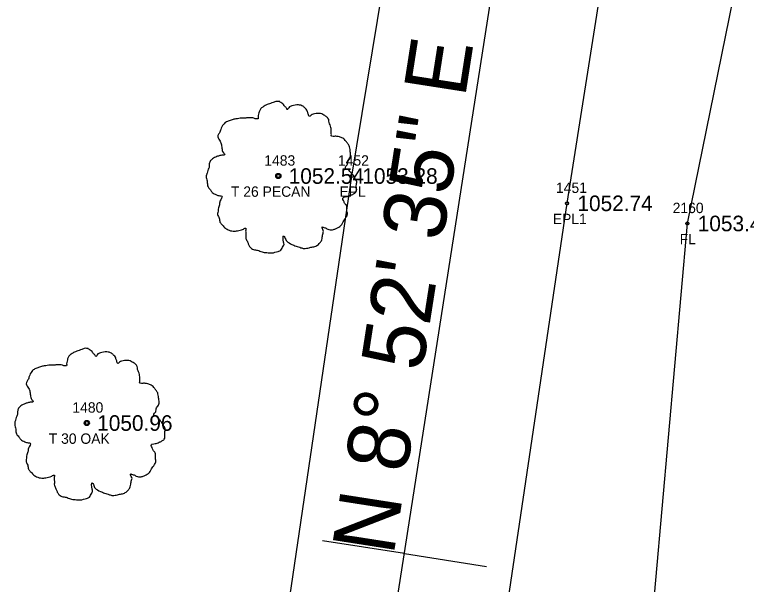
# Model space of a CAD drawing. Extents: x 1578957 to 1581675, y 1115963 to 1120391.
# Drawn here: x 1579746.4 to 1579816.9, y 1117901.5 to 1117956.4 of the extents above; entities that cross this region are included whole.
import ezdxf

# ---------------------------------------------------------------- set-up
doc = ezdxf.new("R2010")
doc.units = 0
for name, color, linetype in [('RD_EX_Fence_Other', 7, 'Continuous'), ('RD_EX_Fence_Other_txCode', 7, 'Continuous'), ('RD_EX_Road', 7, 'Continuous'), ('RD_EX_Road_txCode', 7, 'Continuous'), ('RD_EX_TX_Fence_Other_ELEV', 7, 'Continuous'), ('RD_EX_TX_Road_ELEV', 7, 'Continuous'), ('RD_EX_TX_VEG_ELEV', 7, 'Continuous'), ('RD_EX_VEG', 7, 'Continuous'), ('RD_EX_VEG_txCode', 7, 'Continuous'), ('RD_HC_Cl', 7, 'Continuous'), ('RD_HC_Data', 7, 'Continuous'), ('RD_HC_Data_Tic', 7, 'Continuous'), ('RD_SMD_Locator', 7, 'Continuous')]:
    doc.layers.add(name, color=color, linetype=linetype)

msp = doc.modelspace()

# ---------------------------------------------------------------- linework, layer by layer
at = {"layer": 'RD_EX_Fence_Other'}
msp.add_lwpolyline([(1579823.104, 1118041.087), (1579819.64, 1117977.762), (1579811.21, 1117936.274), (1579806.912, 1117888.201), (1579805.65, 1117872.977), (1579810.216, 1117834.804), (1579821.355, 1117805.105), (1579835.234, 1117784.194), (1579851.403, 1117768.05), (1579868.554, 1117757.557), (1579908.33, 1117744.227), (1579949.735, 1117742.637), (1579998.853, 1117745.107), (1580033.637, 1117749.157), (1580057.075, 1117744.228), (1580092.078, 1117730.794), (1580117.524, 1117724.619), (1580141.715, 1117727.925), (1580159.983, 1117735.31), (1580192.445, 1117760.446), (1580226.972, 1117787.769), (1580271.309, 1117822.486), (1580302.096, 1117858.032)], dxfattribs=at)
at = {"layer": 'RD_EX_Road'}
for points in [[(1580132.914, 1117689.949), (1580126.197, 1117690.713), (1580104.514, 1117701.773), (1580054.231, 1117722.915), (1579999.655, 1117728.645), (1579947.034, 1117725.641), (1579902.617, 1117727.901), (1579859.282, 1117741.23), (1579828.335, 1117764.868), (1579804.422, 1117802.726), (1579793.197, 1117845.912), (1579792.758, 1117891.982), (1579799.628, 1117938.215), (1579807.414, 1117987.508), (1579809.684, 1118039.768), (1579804.464, 1118093.359), (1579794.793, 1118143.944)], [(1580121.995, 1117647.598), (1580119.902, 1117658.172), (1580108.554, 1117670.894), (1580093.888, 1117680.496), (1580047.657, 1117700.115), (1579998.943, 1117706.513), (1579949.017, 1117704.446), (1579899.181, 1117706.754), (1579851.312, 1117721.596), (1579810.789, 1117752.923), (1579804.028, 1117759.706), (1579792.304, 1117778.187), (1579787.439, 1117787.947), (1579779.119, 1117811.184), (1579772.603, 1117842.297), (1579771.808, 1117848.588), (1579770.145, 1117878.236), (1579771.725, 1117892.019), (1579778.922, 1117940.842), (1579785.853, 1117982.888), (1579786.73, 1117990.339), (1579789.156, 1118040.245), (1579783.452, 1118089.738), (1579774.288, 1118139.394)]]:
    msp.add_lwpolyline(points, dxfattribs=at)
at = {"layer": 'RD_EX_VEG'}
for centre, radius in [((1579771.829, 1117940.842), 0.25), ((1579771.816, 1117940.823), 0.0001), ((1579753.39, 1117917.061), 0.25), ((1579753.377, 1117917.042), 0.0001)]:
    msp.add_circle(centre, radius, dxfattribs=at)
for points in [[(1579771.96, 1117948.009), (1579771.661, 1117948.034), (1579771.336, 1117947.934), (1579771.086, 1117947.835), (1579770.861, 1117947.76), (1579770.636, 1117947.66), (1579770.336, 1117947.485), (1579770.111, 1117947.285), (1579769.986, 1117947.035), (1579769.936, 1117946.81), (1579769.886, 1117946.535), (1579769.886, 1117946.36), (1579769.761, 1117946.335), (1579769.611, 1117946.36), (1579769.362, 1117946.435), (1579769.112, 1117946.435), (1579768.862, 1117946.435), (1579768.512, 1117946.41), (1579768.162, 1117946.41), (1579767.887, 1117946.36), (1579767.562, 1117946.31), (1579767.188, 1117946.185), (1579766.838, 1117946.06), (1579766.538, 1117945.81), (1579766.288, 1117945.336), (1579766.163, 1117944.986), (1579766.013, 1117944.736), (1579766.163, 1117944.286), (1579766.338, 1117943.936), (1579766.363, 1117943.736), (1579766.438, 1117943.312), (1579766.538, 1117943.087), (1579766.663, 1117942.887), (1579766.588, 1117942.862), (1579766.213, 1117942.812), (1579765.913, 1117942.712), (1579765.488, 1117942.487), (1579765.263, 1117942.262), (1579765.163, 1117941.937), (1579765.138, 1117941.587), (1579765.039, 1117941.387), (1579764.964, 1117941.112), (1579764.939, 1117941.037), (1579764.889, 1117940.713), (1579764.989, 1117940.263), (1579765.014, 1117939.913), (1579765.138, 1117939.688), (1579765.288, 1117939.513), (1579765.463, 1117939.263), (1579765.863, 1117939.038), (1579766.188, 1117938.938), (1579766.388, 1117938.913), (1579766.213, 1117938.414), (1579766.163, 1117938.064), (1579766.038, 1117937.664), (1579766.038, 1117937.589), (1579765.988, 1117937.114), (1579766.138, 1117936.789), (1579766.213, 1117936.415), (1579766.388, 1117936.19), (1579766.663, 1117935.89), (1579766.988, 1117935.665), (1579767.487, 1117935.54), (1579767.887, 1117935.565), (1579768.462, 1117935.74), (1579768.712, 1117935.815), (1579768.687, 1117935.64), (1579768.712, 1117935.265), (1579768.712, 1117934.84), (1579768.862, 1117934.515), (1579768.962, 1117934.24), (1579769.112, 1117933.991), (1579769.437, 1117933.766), (1579769.836, 1117933.691), (1579770.261, 1117933.541), (1579770.711, 1117933.466), (1579771.211, 1117933.441), (1579771.811, 1117933.591), (1579772.085, 1117933.716), (1579772.185, 1117933.891), (1579772.385, 1117934.265), (1579772.335, 1117934.49), (1579772.36, 1117935.09), (1579772.46, 1117934.915), (1579772.635, 1117934.565), (1579773.135, 1117934.265), (1579773.535, 1117934.091), (1579774.01, 1117933.941), (1579774.309, 1117933.866), (1579774.784, 1117933.941), (1579775.159, 1117934.016), (1579775.534, 1117934.141), (1579775.834, 1117934.415), (1579776.009, 1117934.69), (1579776.059, 1117934.965), (1579776.134, 1117935.34), (1579776.184, 1117935.515)], [(1579776.184, 1117935.515), (1579776.109, 1117935.69), (1579776.059, 1117935.94), (1579776.134, 1117935.915), (1579776.309, 1117935.865), (1579776.583, 1117935.74), (1579776.808, 1117935.665), (1579777.133, 1117935.69), (1579777.408, 1117935.79), (1579777.858, 1117936.065), (1579778.133, 1117936.539), (1579778.408, 1117936.939), (1579778.483, 1117937.264), (1579778.433, 1117937.489), (1579778.408, 1117937.989), (1579778.208, 1117938.239), (1579778.158, 1117938.364), (1579778.058, 1117938.763), (1579778.133, 1117938.813), (1579778.408, 1117938.863), (1579778.782, 1117938.988), (1579779.057, 1117939.113), (1579779.282, 1117939.288), (1579779.357, 1117939.513), (1579779.332, 1117939.913), (1579779.382, 1117940.313), (1579779.307, 1117940.463), (1579779.207, 1117940.613), (1579779.132, 1117940.813), (1579778.982, 1117940.962), (1579778.882, 1117941.112), (1579778.782, 1117941.212), (1579778.658, 1117941.362), (1579778.483, 1117941.487), (1579778.333, 1117941.537), (1579778.283, 1117941.687), (1579778.433, 1117941.887), (1579778.483, 1117941.987), (1579778.508, 1117942.212), (1579778.733, 1117942.562), (1579778.782, 1117942.962), (1579778.733, 1117943.386), (1579778.683, 1117943.661), (1579778.533, 1117943.936), (1579778.333, 1117944.186), (1579778.208, 1117944.361), (1579778.033, 1117944.486), (1579777.708, 1117944.611), (1579777.458, 1117944.661), (1579777.108, 1117944.661), (1579776.908, 1117944.711), (1579776.933, 1117944.761), (1579776.933, 1117944.911), (1579776.933, 1117945.186), (1579776.858, 1117945.635), (1579776.708, 1117946.135), (1579776.708, 1117946.16), (1579776.608, 1117946.41), (1579776.384, 1117946.61), (1579776.209, 1117946.71), (1579776.009, 1117946.835), (1579775.759, 1117946.86), (1579775.459, 1117946.86), (1579775.184, 1117946.81), (1579774.984, 1117946.71), (1579774.809, 1117946.585), (1579774.734, 1117946.735), (1579774.634, 1117947.035), (1579774.584, 1117947.185), (1579774.434, 1117947.36), (1579774.21, 1117947.56), (1579773.76, 1117947.685), (1579773.135, 1117947.61), (1579772.835, 1117947.41), (1579772.685, 1117947.235), (1579772.635, 1117947.36), (1579772.435, 1117947.56), (1579772.335, 1117947.735), (1579772.16, 1117947.86), (1579772.01, 1117947.959), (1579771.91, 1117948.009)], [(1579753.522, 1117924.228), (1579753.222, 1117924.253), (1579752.897, 1117924.153), (1579752.647, 1117924.053), (1579752.422, 1117923.978), (1579752.197, 1117923.878), (1579751.897, 1117923.703), (1579751.672, 1117923.503), (1579751.547, 1117923.253), (1579751.497, 1117923.028), (1579751.448, 1117922.753), (1579751.448, 1117922.578), (1579751.323, 1117922.553), (1579751.173, 1117922.578), (1579750.923, 1117922.653), (1579750.673, 1117922.653), (1579750.423, 1117922.653), (1579750.073, 1117922.628), (1579749.723, 1117922.628), (1579749.448, 1117922.578), (1579749.124, 1117922.529), (1579748.749, 1117922.404), (1579748.399, 1117922.279), (1579748.099, 1117922.029), (1579747.849, 1117921.554), (1579747.724, 1117921.204), (1579747.574, 1117920.954), (1579747.724, 1117920.504), (1579747.899, 1117920.154), (1579747.924, 1117919.955), (1579747.999, 1117919.53), (1579748.099, 1117919.305), (1579748.224, 1117919.105), (1579748.149, 1117919.08), (1579747.774, 1117919.03), (1579747.474, 1117918.93), (1579747.049, 1117918.705), (1579746.825, 1117918.48), (1579746.725, 1117918.155), (1579746.7, 1117917.806), (1579746.6, 1117917.606), (1579746.525, 1117917.331), (1579746.5, 1117917.256), (1579746.45, 1117916.931), (1579746.55, 1117916.481), (1579746.575, 1117916.131), (1579746.7, 1117915.906), (1579746.85, 1117915.731), (1579747.024, 1117915.482), (1579747.424, 1117915.257), (1579747.749, 1117915.157), (1579747.949, 1117915.132), (1579747.774, 1117914.632), (1579747.724, 1117914.282), (1579747.599, 1117913.882), (1579747.599, 1117913.807), (1579747.549, 1117913.333), (1579747.699, 1117913.008), (1579747.774, 1117912.633), (1579747.949, 1117912.408), (1579748.224, 1117912.108), (1579748.549, 1117911.883), (1579749.049, 1117911.758), (1579749.448, 1117911.783), (1579750.023, 1117911.958), (1579750.273, 1117912.033), (1579750.248, 1117911.858), (1579750.273, 1117911.483), (1579750.273, 1117911.059), (1579750.423, 1117910.734), (1579750.523, 1117910.459), (1579750.673, 1117910.209), (1579750.998, 1117909.984), (1579751.398, 1117909.909), (1579751.822, 1117909.759), (1579752.272, 1117909.684), (1579752.772, 1117909.659), (1579753.372, 1117909.809), (1579753.647, 1117909.934), (1579753.747, 1117910.109), (1579753.946, 1117910.484), (1579753.896, 1117910.709), (1579753.921, 1117911.308), (1579754.021, 1117911.133), (1579754.196, 1117910.784), (1579754.696, 1117910.484), (1579755.096, 1117910.309), (1579755.571, 1117910.159), (1579755.871, 1117910.084), (1579756.345, 1117910.159), (1579756.72, 1117910.234), (1579757.095, 1117910.359), (1579757.395, 1117910.634), (1579757.57, 1117910.909), (1579757.62, 1117911.183), (1579757.695, 1117911.558), (1579757.745, 1117911.733)], [(1579757.745, 1117911.733), (1579757.67, 1117911.908), (1579757.62, 1117912.158), (1579757.695, 1117912.133), (1579757.87, 1117912.083), (1579758.145, 1117911.958), (1579758.37, 1117911.883), (1579758.694, 1117911.908), (1579758.969, 1117912.008), (1579759.419, 1117912.283), (1579759.694, 1117912.758), (1579759.969, 1117913.158), (1579760.044, 1117913.482), (1579759.994, 1117913.707), (1579759.969, 1117914.207), (1579759.769, 1117914.457), (1579759.719, 1117914.582), (1579759.619, 1117914.982), (1579759.694, 1117915.032), (1579759.969, 1117915.082), (1579760.344, 1117915.207), (1579760.619, 1117915.332), (1579760.843, 1117915.507), (1579760.918, 1117915.731), (1579760.893, 1117916.131), (1579760.943, 1117916.531), (1579760.868, 1117916.681), (1579760.768, 1117916.831), (1579760.693, 1117917.031), (1579760.544, 1117917.181), (1579760.444, 1117917.331), (1579760.344, 1117917.431), (1579760.219, 1117917.581), (1579760.044, 1117917.706), (1579759.894, 1117917.756), (1579759.844, 1117917.905), (1579759.994, 1117918.105), (1579760.044, 1117918.205), (1579760.069, 1117918.43), (1579760.294, 1117918.78), (1579760.344, 1117919.18), (1579760.294, 1117919.605), (1579760.244, 1117919.88), (1579760.094, 1117920.154), (1579759.894, 1117920.404), (1579759.769, 1117920.579), (1579759.594, 1117920.704), (1579759.269, 1117920.829), (1579759.019, 1117920.879), (1579758.669, 1117920.879), (1579758.469, 1117920.929), (1579758.494, 1117920.979), (1579758.494, 1117921.129), (1579758.494, 1117921.404), (1579758.419, 1117921.854), (1579758.27, 1117922.354), (1579758.27, 1117922.379), (1579758.17, 1117922.628), (1579757.945, 1117922.828), (1579757.77, 1117922.928), (1579757.57, 1117923.053), (1579757.32, 1117923.078), (1579757.02, 1117923.078), (1579756.745, 1117923.028), (1579756.545, 1117922.928), (1579756.37, 1117922.803), (1579756.295, 1117922.953), (1579756.195, 1117923.253), (1579756.145, 1117923.403), (1579755.996, 1117923.578), (1579755.771, 1117923.778), (1579755.321, 1117923.903), (1579754.696, 1117923.828), (1579754.396, 1117923.628), (1579754.246, 1117923.453), (1579754.196, 1117923.578), (1579753.996, 1117923.778), (1579753.896, 1117923.953), (1579753.722, 1117924.078), (1579753.572, 1117924.178), (1579753.472, 1117924.228)]]:
    msp.add_spline(points, degree=3, dxfattribs=at)
at = {"layer": 'RD_HC_Cl'}
msp.add_line((1579781.145, 1117886.379), (1579795.16, 1117976.12), dxfattribs=at)
at = {"layer": 'RD_HC_Data_Tic'}
for q in [(1579776.07, 1117905.73), (1579791.879, 1117903.261)]:
    msp.add_line((1579783.974, 1117904.496), q, dxfattribs=at)
at = {"layer": 'RD_SMD_Locator'}
for centre in [(1579771.829, 1117940.842), (1579778.922, 1117940.842), (1579799.628, 1117938.215), (1579811.21, 1117936.274), (1579753.39, 1117917.06)]:
    msp.add_circle(centre, 0.15, dxfattribs=at)

# ---------------------------------------------------------------- texts
at = {"layer": 'RD_EX_Fence_Other_txCode'}
for s, p in [('2160', (1579809.8, 1117937.274)), ('FL', (1579810.478, 1117934.274))]:
    msp.add_text(s, height=1, dxfattribs=at).set_placement(p)
at = {"layer": 'RD_EX_Road_txCode'}
for s, p in [('1452', (1579777.576, 1117941.842)), ('1451', (1579798.565, 1117939.215)), ('EPL', (1579777.717, 1117938.842)), ('EPL1', (1579798.258, 1117936.215))]:
    msp.add_text(s, height=1, dxfattribs=at).set_placement(p)
at = {"layer": 'RD_EX_TX_Fence_Other_ELEV'}
msp.add_text('1053.47', height=1.5, dxfattribs=at).set_placement((1579812.21, 1117935.524))
at = {"layer": 'RD_EX_TX_Road_ELEV'}
for s, p in [('1053.28', (1579779.922, 1117940.092)), ('1052.74', (1579800.628, 1117937.465))]:
    msp.add_text(s, height=1.5, dxfattribs=at).set_placement(p)
at = {"layer": 'RD_EX_TX_VEG_ELEV'}
for s, p in [('1052.54', (1579772.829, 1117940.092)), ('1050.96', (1579754.39, 1117916.31))]:
    msp.add_text(s, height=1.5, dxfattribs=at).set_placement(p)
at = {"layer": 'RD_EX_VEG_txCode'}
for s, p in [('1483', (1579770.482, 1117941.842)), ('T 26 PECAN', (1579767.269, 1117938.842)), ('1480', (1579752.004, 1117918.06)), ('T 30 OAK', (1579749.728, 1117915.06))]:
    msp.add_text(s, height=1, dxfattribs=at).set_placement(p)
at = {"layer": 'RD_HC_Data'}
msp.add_text('N 8%%d 52\' 35" E', height=6, rotation=81.12359, dxfattribs=at).set_placement((1579782.918, 1117904.214))

doc.saveas('drawing.dxf')
